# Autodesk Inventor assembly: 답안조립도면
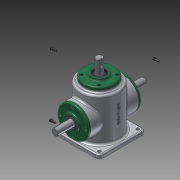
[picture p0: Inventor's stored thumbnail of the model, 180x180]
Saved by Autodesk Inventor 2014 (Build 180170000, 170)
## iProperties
Created: 2015-10
Part Number: 답안조립도면
Document SubType Name: Assembly
Designer: USER
Author: USER
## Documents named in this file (14)
- C:\Users\USER\Desktop\451007V1012\답안조립도면.iam
- C:\Users\USER\Desktop\451007V1012\본체.ipt
- C:\Users\USER\Desktop\451007V1012\M4.ipt
- C:\Users\USER\Desktop\451007V1012\메인 베벨기어.ipt
- C:\Users\USER\Desktop\451007V1012\메인 축.ipt
- 메인 축.ipt
- C:\Users\USER\Desktop\451007V1012\베어링 6203.ipt
- C:\Users\USER\Desktop\451007V1012\서브 베벨기어.ipt
- C:\Users\USER\Desktop\451007V1012\서브 축.ipt
- 서브 축.ipt
- C:\Users\USER\Desktop\451007V1012\오일실.ipt
- C:\Users\USER\Desktop\451007V1012\커버.ipt
- C:\Users\USER\Desktop\451007V1012\키 4x4.ipt
- C:\Users\USER\Desktop\451007V1012\키 5x5.ipt
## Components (3 placed, 1 different names)
1. M4:1
2. M4:2
3. M4:3
